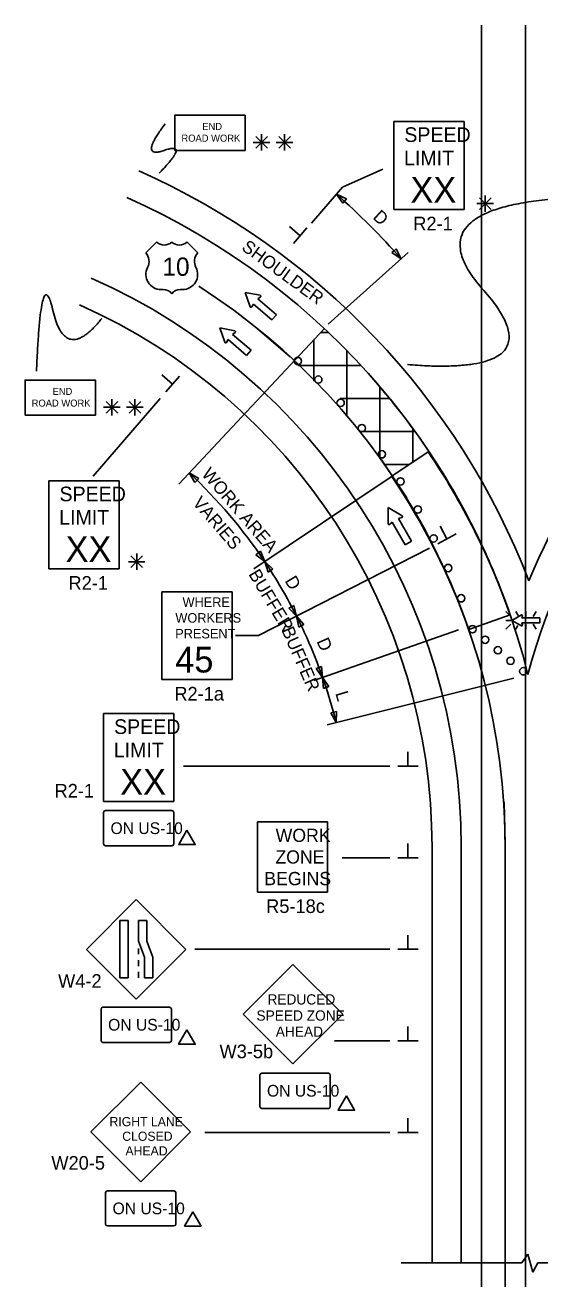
# Model space of a CAD drawing. Extents: x 16729 to 18475, y 5718 to 6974.
# Drawn here: x 16731 to 17013, y 6289 to 6974 of the extents above; entities that cross this region are included whole.
import ezdxf

# ---------------------------------------------------------------- set-up
doc = ezdxf.new("R2010")
doc.units = 0
for name, color, linetype in [('ALI_LEGAL_EX', 7, 'Continuous'), ('MT_SCRATCH_LEVEL_A', 7, 'Continuous'), ('MT_SCRATCH_LEVEL_E', 7, 'Continuous'), ('PAVT_EDGE_EX', 7, 'Continuous'), ('TRAFFIC_SIGNS_PR', 7, 'Continuous'), ('TYPICAL_EX', 7, 'Continuous'), ('TYPICAL_TEXT_DIMEN_PR', 7, 'Continuous')]:
    doc.layers.add(name, color=color, linetype=linetype)

msp = doc.modelspace()

# ---------------------------------------------------------------- linework, layer by layer
at = {"layer": 'ALI_LEGAL_EX'}
for p, q in [((16980.68, 6974.12), (16980.68, 6155.98)), ((17004.68, 6974.12), (17004.68, 6155.98)), ((16980.68, 6877.04), (16980.68, 6013.12)), ((17004.68, 6877.04), (17004.68, 6013.12)), ((16993.65, 6024.8), (16993.65, 6525.15))]:
    msp.add_line(p, q, dxfattribs=at)
for points in [[(17004.68, 6949.12), (17004.68, 6974.12)], [(16876.06, 6792.99), (16857.11, 6809.3)], [(16939.89, 6715.82), (16925.99, 6736.59)], [(16993.6, 6524.8), (16993.65, 6525.15), (16993.08, 6549.79)], [(16993.65, 6424.8), (16993.65, 6449.8)], [(16993.7, 6349.8), (16993.7, 6374.8)]]:
    msp.add_lwpolyline(points, dxfattribs=at)
msp.add_arc((16629.65, 6525.15), 364, 0, 57.29578, dxfattribs=at)
at = {"layer": 'MT_SCRATCH_LEVEL_A'}
for p, q in [((16889.15, 6779.64), (16889.15, 6802.33)), ((16892.78, 6806.2), (16897.14, 6806.2)), ((16907.15, 6760.43), (16907.15, 6796.32)), ((16880.47, 6788.2), (16914.86, 6788.2)), ((16925.15, 6737.43), (16925.15, 6776.33)), ((16903.28, 6770.2), (16930.27, 6770.2)), ((16943.15, 6735.46), (16943.15, 6753.45)), ((16914.07, 6752.2), (16944.07, 6752.2)), ((16927.54, 6734.2), (16941.3, 6734.2))]:
    msp.add_line(p, q, dxfattribs=at)
for start, end in [(24.11224, 41.84707), (19.31994, 24.11224)]:
    msp.add_arc((16629.65, 6525.15), 388, start, end, dxfattribs=at)
at = {"layer": 'MT_SCRATCH_LEVEL_E'}
for p, q in [((16859.73, 6826.53), (16851.54, 6828.11)), ((16851.54, 6828.11), (16854.35, 6820.27)), ((16855.18, 6820.19), (16856.1, 6821.74)), ((16856.1, 6821.74), (16866.15, 6813.1)), ((16858.54, 6824.58), (16859.94, 6825.72)), ((16868.59, 6815.93), (16858.54, 6824.58)), ((16866.15, 6813.1), (16868.59, 6815.93)), ((16845.92, 6807.1), (16837.72, 6808.67)), ((16837.72, 6808.67), (16840.53, 6800.84)), ((16841.36, 6800.76), (16842.28, 6802.31)), ((16842.28, 6802.31), (16852.33, 6793.66)), ((16844.72, 6805.15), (16846.12, 6806.29)), ((16854.77, 6796.5), (16844.72, 6805.15)), ((16852.33, 6793.66), (16854.77, 6796.5))]:
    msp.add_line(p, q, dxfattribs=at)
for centre, start, end in [((16859.64, 6826.07), 309.33612, 79.07304), ((16854.78, 6820.43), 199.72477, 329.26374), ((16840.97, 6801), 199.72477, 329.26374), ((16845.82, 6806.64), 309.33612, 79.07304)]:
    msp.add_arc(centre, 0.463, start, end, dxfattribs=at)
at = {"layer": 'PAVT_EDGE_EX'}
for p, q in [((16951.5, 6741.11), (16931.62, 6727.65)), ((16973.74, 6643.97), (16996.39, 6651.91)), ((16953.65, 6525.15), (16953.65, 6298.02)), ((16969.65, 6525.15), (16969.65, 6298.02))]:
    msp.add_line(p, q, dxfattribs=at)
for centre, radius, start, end in [((16629.65, 6525.15), 404, 21.09612, 66.09058), ((16629.65, 6525.15), 388, 14.04823, 66.09058), ((16629.65, 6525.15), 340, 0, 66.09058), ((17357.65, 6525.15), 380, 124.38118, 157.50106), ((16629.65, 6525.15), 324, 0, 66.09058), ((17357.65, 6525.15), 364, 124.38118, 165.0045), ((16630.24, 6523.54), 388, 19.31995, 34.10709), ((16630.24, 6523.54), 363.99, 19.31995, 34.10709)]:
    msp.add_arc(centre, radius, start, end, dxfattribs=at)
at = {"layer": 'TRAFFIC_SIGNS_PR'}
for p, q in [((16932.75, 6921.42), (16971.15, 6921.42)), ((16932.75, 6873.42), (16932.75, 6921.42)), ((16971.15, 6873.42), (16971.15, 6921.42)), ((16932.75, 6873.42), (16971.15, 6873.42)), ((16744.34, 6725.16), (16782.74, 6725.16)), ((16744.34, 6677.16), (16744.34, 6725.16)), ((16782.74, 6677.16), (16782.74, 6725.16)), ((16744.34, 6677.16), (16782.74, 6677.16)), ((16806.03, 6664.64), (16844.43, 6664.64)), ((16806.03, 6616.64), (16806.03, 6664.64)), ((16844.43, 6616.64), (16844.43, 6664.64)), ((16993.92, 6653.82), (16996.74, 6651.01)), ((17000.64, 6651.64), (16999.38, 6653.82)), ((17004.82, 6651.01), (17004.82, 6653.82)), ((17008.96, 6651.01), (17010.59, 6653.82)), ((16996.74, 6648.97), (16993.92, 6648.97)), ((16993.92, 6644.12), (16996.74, 6646.94)), ((16999.35, 6644.12), (17000.56, 6646.21)), ((17004.82, 6646.94), (17004.82, 6644.12)), ((17010.61, 6644.12), (17008.98, 6646.94)), ((16806.03, 6616.64), (16844.43, 6616.64)), ((16774.16, 6598.07), (16812.56, 6598.07)), ((16774.16, 6550.07), (16774.16, 6598.07)), ((16812.56, 6550.07), (16812.56, 6598.07)), ((16774.16, 6550.07), (16812.56, 6550.07)), ((16774.16, 6544.07), (16774.16, 6526.87)), ((16775.16, 6545.07), (16811.56, 6545.07)), ((16812.56, 6544.07), (16812.56, 6526.87)), ((16858.21, 6500.59), (16858.21, 6538.99)), ((16858.21, 6538.99), (16896.61, 6538.99)), ((16896.61, 6500.59), (16896.61, 6538.99)), ((16775.16, 6525.87), (16811.56, 6525.87)), ((16858.21, 6500.59), (16896.61, 6500.59)), ((16792.03, 6496.45), (16764.88, 6469.29)), ((16819.18, 6469.29), (16792.03, 6496.45)), ((16764.88, 6469.29), (16792.03, 6442.14)), ((16792.03, 6442.14), (16819.18, 6469.29)), ((16793.27, 6469.78), (16793.27, 6466.58)), ((16793.27, 6463.38), (16793.27, 6460.18)), ((16877.68, 6461), (16850.53, 6433.84)), ((16904.84, 6433.84), (16877.68, 6461)), ((16793.27, 6456.98), (16793.27, 6453.78)), ((16773.83, 6437.7), (16810.23, 6437.7)), ((16772.83, 6436.7), (16772.83, 6419.49)), ((16811.23, 6436.7), (16811.23, 6419.49)), ((16850.53, 6433.84), (16877.68, 6406.69)), ((16877.68, 6406.69), (16904.84, 6433.84)), ((16773.83, 6418.49), (16810.23, 6418.49)), ((16794.47, 6396.7), (16767.32, 6369.55)), ((16821.62, 6369.55), (16794.47, 6396.7)), ((16859.64, 6400.65), (16859.64, 6383.45)), ((16860.64, 6401.65), (16897.04, 6401.65)), ((16898.04, 6400.65), (16898.04, 6383.45)), ((16860.64, 6382.45), (16897.04, 6382.45)), ((16767.32, 6369.55), (16794.47, 6342.4)), ((16794.47, 6342.4), (16821.62, 6369.55)), ((16775.27, 6336.4), (16775.27, 6319.2)), ((16776.27, 6337.4), (16812.67, 6337.4)), ((16813.67, 6336.4), (16813.67, 6319.2)), ((16776.27, 6318.2), (16812.67, 6318.2))]:
    msp.add_line(p, q, dxfattribs=at)
for points in [[(16813.12, 6905.7), (16851.52, 6905.7), (16851.52, 6924.9), (16813.12, 6924.9)], [(16731.31, 6761), (16769.71, 6761), (16769.71, 6780.2), (16731.31, 6780.2)], [(16783.14, 6485.03), (16783.14, 6453.78), (16787.63, 6453.78), (16787.63, 6485.03)], [(16793.27, 6485.03), (16793.27, 6473.85), (16796.62, 6464.97), (16796.62, 6453.78), (16801.11, 6453.78), (16801.11, 6464.97), (16797.76, 6473.85), (16797.76, 6485.03)]]:
    msp.add_lwpolyline(points, close=True, dxfattribs=at)
for points in [[(17002.5, 6651.99), (16997.19, 6648.97), (17002.5, 6645.93)], [(17003, 6646.29), (17002.77, 6647.59), (17012.49, 6647.59), (17012.49, 6650.33), (17002.77, 6650.33), (17003, 6651.63)]]:
    msp.add_lwpolyline(points, dxfattribs=at)
for centre in [(16880.34, 6790.64), (16891.53, 6780.47), (16903.73, 6767.76), (16915.33, 6753.99), (16926.23, 6739.67), (16936.42, 6724.84), (16945.86, 6709.51), (16954.54, 6693.75), (16962.44, 6677.57), (16969.53, 6661.03), (16975.8, 6644.16), (16982.72, 6638.4), (16989.65, 6632.65), (16996.57, 6626.9), (17003.5, 6621.15)]:
    msp.add_circle(centre, 2, dxfattribs=at)
for centre, radius, start, end in [((17002.66, 6651.69), 0.341, 350.73078, 118.89165), ((17002.66, 6646.23), 0.341, 241.48329, 9.95933), ((16775.16, 6544.07), 1, 90, 180), ((16811.56, 6544.07), 1, 0, 90), ((16775.16, 6526.87), 1, 180, 270), ((16811.56, 6526.87), 1, 270, 0), ((16773.83, 6436.7), 1, 90, 180), ((16810.23, 6436.7), 1, 0, 90), ((16773.83, 6419.49), 1, 180, 270), ((16810.23, 6419.49), 1, 270, 0), ((16860.64, 6400.65), 1, 90, 180), ((16897.04, 6400.65), 1, 0, 90), ((16860.64, 6383.45), 1, 180, 270), ((16897.04, 6383.45), 1, 270, 0), ((16776.27, 6336.4), 1, 90, 180), ((16812.67, 6336.4), 1, 0, 90), ((16776.27, 6319.2), 1, 180, 270), ((16812.67, 6319.2), 1, 270, 0)]:
    msp.add_arc(centre, radius, start, end, dxfattribs=at)
at = {"layer": 'TYPICAL_EX'}
for p, q in [((16797.33, 6849.74), (16803.22, 6855.64)), ((16825.62, 6849.74), (16819.73, 6855.64)), ((16805.57, 6829.68), (16806.75, 6829.68)), ((16817.38, 6829.68), (16816.2, 6829.68))]:
    msp.add_line(p, q, dxfattribs=at)
for centre, radius, start, end in [((16807.35, 6859.93), 5.96, 226.14041, 313.85958), ((16815.6, 6859.93), 5.96, 226.14042, 313.85959), ((16791.74, 6845.02), 7.31, 333.09768, 40.19361), ((16831.21, 6845.02), 7.31, 139.80639, 206.90233), ((16805.58, 6837.93), 8.24, 152.6698, 269.90132), ((16817.36, 6837.93), 8.24, 270.09868, 27.3302), ((16806.76, 6823.78), 5.91, 37.1038, 90.13853), ((16816.18, 6823.78), 5.91, 89.86147, 142.8962)]:
    msp.add_arc(centre, radius, start, end, dxfattribs=at)
at = {"layer": 'TYPICAL_TEXT_DIMEN_PR'}
for p, q in [((16860.55, 6910.07), (16856.01, 6910.07)), ((16857.36, 6913.26), (16863.73, 6906.88)), ((16863.73, 6913.26), (16857.36, 6906.88)), ((16860.55, 6910.07), (16860.55, 6914.53)), ((16860.55, 6910.07), (16863.73, 6910.07)), ((16860.55, 6910.07), (16865.02, 6910.07)), ((16860.55, 6910.07), (16860.55, 6905.57)), ((16873.1, 6910.07), (16868.57, 6910.07)), ((16876.29, 6913.26), (16869.91, 6906.88)), ((16869.92, 6913.26), (16876.29, 6906.88)), ((16873.1, 6910.07), (16873.1, 6914.53)), ((16873.1, 6910.07), (16876.29, 6910.07)), ((16873.1, 6910.07), (16877.58, 6910.07)), ((16873.1, 6910.07), (16873.1, 6905.57)), ((16904.77, 6885.64), (16926.81, 6895.48)), ((16904.77, 6885.64), (16887.79, 6865.95)), ((16904.87, 6876.79), (16901.46, 6881.81)), ((16901.46, 6881.81), (16906.92, 6879.17)), ((16905.9, 6877.98), (16904.87, 6876.79)), ((16906.92, 6879.17), (16905.9, 6877.98)), ((16982.73, 6876.6), (16978.2, 6876.6)), ((16979.55, 6879.79), (16985.92, 6873.42)), ((16985.92, 6879.79), (16979.55, 6873.42)), ((16982.73, 6876.6), (16982.73, 6881.06)), ((16982.73, 6876.6), (16985.92, 6876.6)), ((16982.73, 6876.6), (16987.21, 6876.6)), ((16982.73, 6876.6), (16982.73, 6872.1)), ((16881.6, 6859.03), (16875.71, 6864.12)), ((16885.28, 6863.29), (16877.93, 6854.78)), ((16940.55, 6849.83), (16896.88, 6810.73)), ((16931.74, 6849.82), (16932.91, 6850.86)), ((16936.82, 6846.5), (16931.74, 6849.82)), ((16932.91, 6850.86), (16934.08, 6851.91)), ((16934.08, 6851.91), (16936.82, 6846.5)), ((16894.83, 6808.39), (16815.29, 6723.43)), ((16811.94, 6778.02), (16806.05, 6783.1)), ((16815.62, 6782.27), (16808.27, 6773.76)), ((16805.18, 6770.18), (16768.52, 6727.67)), ((16775.54, 6768.56), (16781.92, 6762.18)), ((16781.92, 6768.56), (16775.54, 6762.18)), ((16778.73, 6765.37), (16778.73, 6769.82)), ((16788.1, 6768.56), (16794.47, 6762.18)), ((16794.47, 6768.56), (16788.1, 6762.18)), ((16791.28, 6765.37), (16791.28, 6769.82)), ((16778.73, 6765.37), (16774.2, 6765.37)), ((16778.73, 6765.37), (16781.92, 6765.37)), ((16778.73, 6765.37), (16783.21, 6765.37)), ((16778.73, 6765.37), (16778.73, 6760.87)), ((16791.28, 6765.37), (16786.75, 6765.37)), ((16791.28, 6765.37), (16794.47, 6765.37)), ((16791.28, 6765.37), (16795.76, 6765.37)), ((16791.28, 6765.37), (16791.28, 6760.87)), ((16824.07, 6724.3), (16821.01, 6729.55)), ((16821.01, 6729.55), (16826.28, 6726.53)), ((16825.18, 6725.42), (16824.07, 6724.3)), ((16826.28, 6726.53), (16825.18, 6725.42)), ((16931.92, 6727.73), (16856.28, 6677.09)), ((16937.27, 6706.11), (16929.6, 6710.62)), ((16929.6, 6710.62), (16929.63, 6701.74)), ((16935.38, 6704.58), (16937.19, 6705.23)), ((16930.44, 6701.36), (16931.91, 6702.59)), ((16931.91, 6702.59), (16938.94, 6690.32)), ((16942.4, 6692.3), (16935.38, 6704.58)), ((16961.8, 6693.51), (16958.09, 6700.36)), ((16938.94, 6690.32), (16942.4, 6692.3)), ((16966.75, 6696.19), (16956.85, 6690.84)), ((16789.12, 6684.2), (16795.49, 6677.82)), ((16795.49, 6684.2), (16789.12, 6677.82)), ((16792.3, 6681.01), (16792.3, 6685.46)), ((16857.47, 6684.86), (16858.73, 6685.79)), ((16862.22, 6681.07), (16857.47, 6684.86)), ((16858.73, 6685.79), (16860, 6686.72)), ((16952.27, 6688.45), (16858.92, 6640.65)), ((16860, 6686.72), (16862.22, 6681.07)), ((16792.3, 6681.01), (16787.77, 6681.01)), ((16792.3, 6681.01), (16795.49, 6681.01)), ((16792.3, 6681.01), (16796.78, 6681.01)), ((16792.3, 6681.01), (16792.3, 6676.51)), ((16864.12, 6675.3), (16862.22, 6681.07)), ((16862.22, 6681.07), (16866.74, 6677.03)), ((16865.43, 6676.16), (16864.12, 6675.3)), ((16866.74, 6677.03), (16865.43, 6676.16)), ((16876.82, 6656.33), (16878.19, 6657.09)), ((16878.19, 6657.09), (16879.67, 6651.21)), ((16875.45, 6655.57), (16876.82, 6656.33)), ((16879.67, 6651.21), (16875.45, 6655.57)), ((16880.79, 6645.3), (16879.64, 6651.26)), ((16879.64, 6651.26), (16883.61, 6646.67)), ((16882.2, 6645.98), (16880.79, 6645.3)), ((16883.61, 6646.67), (16882.2, 6645.98)), ((16968.07, 6643.79), (16889.16, 6616.13)), ((16858.92, 6640.65), (16846.36, 6640.67)), ((16890.4, 6622.75), (16891.88, 6623.29)), ((16893.88, 6617.78), (16890.4, 6622.75)), ((16891.88, 6623.29), (16893.35, 6623.83)), ((16893.35, 6623.83), (16893.88, 6617.78)), ((16894.34, 6611.73), (16893.88, 6617.78)), ((16893.88, 6617.78), (16897.3, 6612.77)), ((16998.34, 6617.4), (16896.42, 6591.9)), ((16895.82, 6612.25), (16894.34, 6611.73)), ((16897.3, 6612.77), (16895.82, 6612.25)), ((16898.33, 6598.42), (16899.85, 6598.8)), ((16901.28, 6593.11), (16898.33, 6598.42)), ((16899.85, 6598.8), (16901.38, 6599.18)), ((16901.38, 6599.18), (16901.28, 6593.11)), ((16940.52, 6569.33), (16940.52, 6577.11)), ((16930.65, 6569.33), (16817.92, 6569.33)), ((16934.9, 6569.33), (16946.15, 6569.33)), ((16940.52, 6519.33), (16940.52, 6527.11)), ((16930.65, 6519.33), (16904.56, 6519.33)), ((16934.9, 6519.33), (16946.15, 6519.33)), ((16940.52, 6469.33), (16940.52, 6477.11)), ((16930.65, 6469.33), (16824.04, 6469.33)), ((16934.9, 6469.33), (16946.15, 6469.33)), ((16940.52, 6419.33), (16940.52, 6427.11)), ((16930.65, 6419.33), (16900.37, 6419.33)), ((16934.9, 6419.33), (16946.15, 6419.33)), ((16940.52, 6369.33), (16940.52, 6377.11)), ((16930.65, 6369.33), (16829.5, 6369.33)), ((16934.9, 6369.33), (16946.15, 6369.33)), ((17005.97, 6302.82), (17002.72, 6298.02)), ((17008.71, 6292.88), (17005.97, 6302.82)), ((17002.72, 6298.02), (16936.78, 6298.02)), ((17011.46, 6298.02), (17008.71, 6292.88)), ((17073.79, 6298.02), (17011.46, 6298.02))]:
    msp.add_line(p, q, dxfattribs=at)
for points in [[(16819.76, 6534.31), (16815.24, 6526.48), (16824.29, 6526.48)], [(16819.72, 6425.28), (16815.2, 6417.45), (16824.25, 6417.45)], [(16906.85, 6389.23), (16902.33, 6381.39), (16911.38, 6381.39)], [(16822.98, 6325.97), (16818.45, 6318.14), (16827.5, 6318.14)]]:
    msp.add_lwpolyline(points, close=True, dxfattribs=at)
for centre, radius, start, end in [((16603.09, 6547.62), 448, 41.84709, 48.24171), ((16629.65, 6525.15), 280, 33.84027, 46.88624), ((16937.01, 6705.69), 0.494, 289.82026, 59.55718), ((16930.12, 6701.75), 0.494, 180.20891, 309.74787), ((16629.65, 6525.15), 280, 26.75746, 33.83921), ((16629.65, 6525.15), 280, 24.11237, 26.76889), ((16629.65, 6525.15), 280, 19.31996, 24.11237), ((16629.65, 6525.15), 280, 14.04822, 19.31996)]:
    msp.add_arc(centre, radius, start, end, dxfattribs=at)
for points in [[(16804.61, 6893.24), (16821.56, 6910.58), (16793.16, 6900.78), (16807.84, 6920.15)], [(17036.03, 6880.07), (16939.73, 6876.74), (17023.71, 6782.03), (16940.29, 6788.65)], [(16773.24, 6813.86), (16753.37, 6789.07), (16740, 6846.38), (16737.56, 6785.01)]]:
    msp.add_open_spline(points, degree=2, dxfattribs=at)

# ---------------------------------------------------------------- texts
at = {"layer": 'TRAFFIC_SIGNS_PR'}
for s, height, p in [('END', 3.831, (16828.12, 6916.83)), ('SPEED', 8, (16938.51, 6910.28)), ('ROAD WORK', 3.831, (16816.73, 6910.44)), ('LIMIT', 8, (16938.35, 6897.48)), ('XX', 14.031, (16941.86, 6877.17)), ('R2-1', 7.44, (16943.42, 6861.98)), ('END', 3.831, (16746.31, 6772.12)), ('ROAD WORK', 3.831, (16734.91, 6765.74)), ('SPEED', 8, (16750.11, 6714.02)), ('LIMIT', 8, (16749.95, 6701.22)), ('XX', 14.031, (16753.45, 6680.91)), ('R2-1', 7.44, (16755.02, 6665.72)), ('WHERE', 5.2, (16817.34, 6656.33)), ('WORKERS', 5.2, (16813.42, 6647.73)), ('PRESENT', 5.2, (16813.35, 6639.13)), ('45', 14.031, (16813.34, 6620.5)), ('R2-1a', 7.44, (16812.88, 6605.2)), ('SPEED', 8, (16779.93, 6586.93)), ('LIMIT', 8, (16779.77, 6574.13)), ('XX', 14.031, (16783.28, 6553.82)), ('R2-1', 7.44, (16747.43, 6552.2)), ('ON US-10', 6.4, (16778, 6532.27)), ('WORK', 7.217, (16868.21, 6527.96)), ('ZONE', 7.217, (16868.09, 6516.15)), ('BEGINS', 7.217, (16862.02, 6504.34)), ('R5-18c', 7.44, (16863.02, 6489.15)), ('W4-2', 7.441, (16749.34, 6448.29)), ('REDUCED', 5.6, (16863.74, 6439.15)), ('ON US-10', 6.401, (16776.67, 6424.9)), ('SPEED ZONE', 5.6, (16857.73, 6430.35)), ('AHEAD', 5.6, (16868.29, 6421.55)), ('W3-5b', 7.44, (16837.54, 6409.84)), ('ON US-10', 6.4, (16863.48, 6388.85)), ('RIGHT LANE', 4.999, (16777.42, 6372.7)), ('CLOSED', 4.999, (16784.4, 6364.71)), ('W20-5', 7.439, (16745.67, 6348.95)), ('AHEAD', 4.999, (16786.15, 6356.71)), ('ON US-10', 6.401, (16779.11, 6324.6))]:
    msp.add_text(s, height=height, dxfattribs=at).set_placement(p)
at = {"layer": 'TYPICAL_EX'}
msp.add_text('10', height=10, dxfattribs=at).set_placement((16806.32, 6837.17))
at = {"layer": 'TYPICAL_TEXT_DIMEN_PR'}
for s, rotation, p in [('D', 317.70486, (16920.86, 6868.69)), ('SHOULDER', 323.95817, (16849.12, 6851.66)), ('WORK AREA', 310.75406, (16827.37, 6728.65)), ('VARIES', 310.75406, (16822.41, 6712.96)), ('BUFFER', 300.95823, (16853.16, 6674.26)), ('D', 300.95823, (16872.96, 6670.63)), ('BUFFER', 293.70432, (16871.25, 6643.71)), ('D', 293.70432, (16890.43, 6637.61)), ('L', 286.68497, (16900.73, 6609.19))]:
    msp.add_text(s, height=7, rotation=rotation, dxfattribs=at).set_placement(p)

doc.saveas('drawing.dxf')
